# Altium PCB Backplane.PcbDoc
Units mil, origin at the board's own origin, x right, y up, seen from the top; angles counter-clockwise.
Board outline 5750 x 1500 mil, 6 copper layers (Top Layer, InternalPlane1, InternalPlane2, InternalPlane3, InternalPlane4, Bottom Layer); 11 components, 85 nets, 180 pads, 5 vias.
Unrouted connection lines stored in the file: 2.
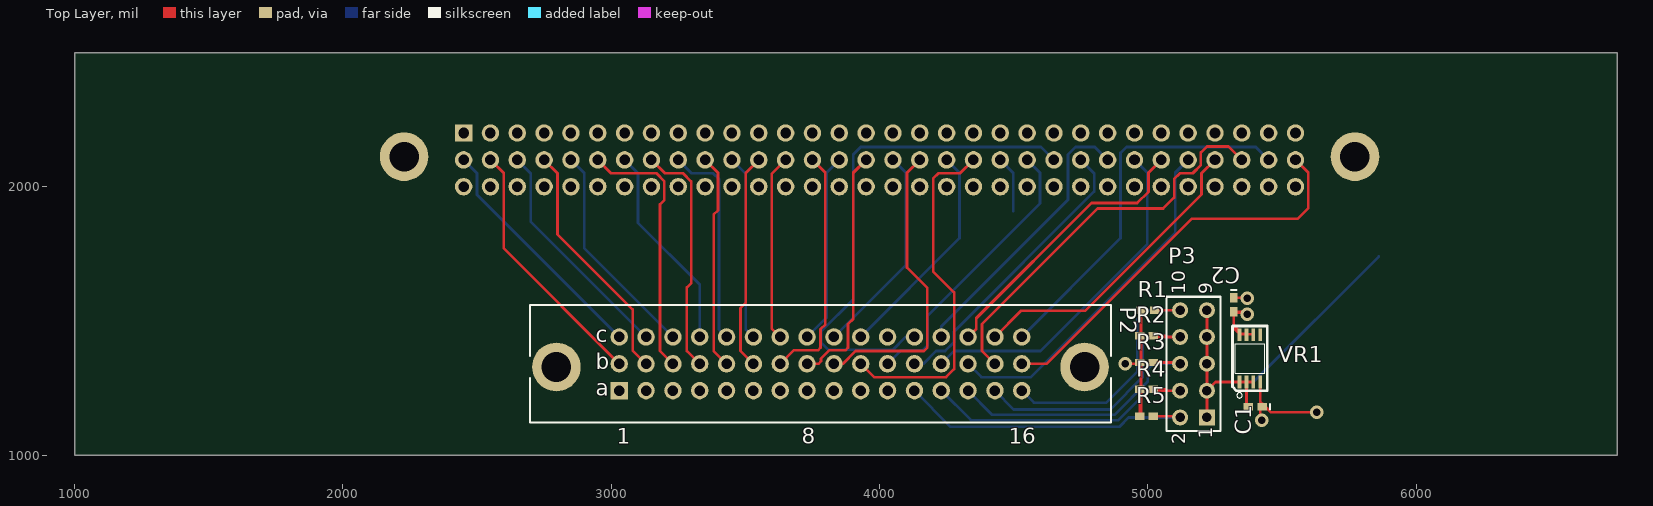
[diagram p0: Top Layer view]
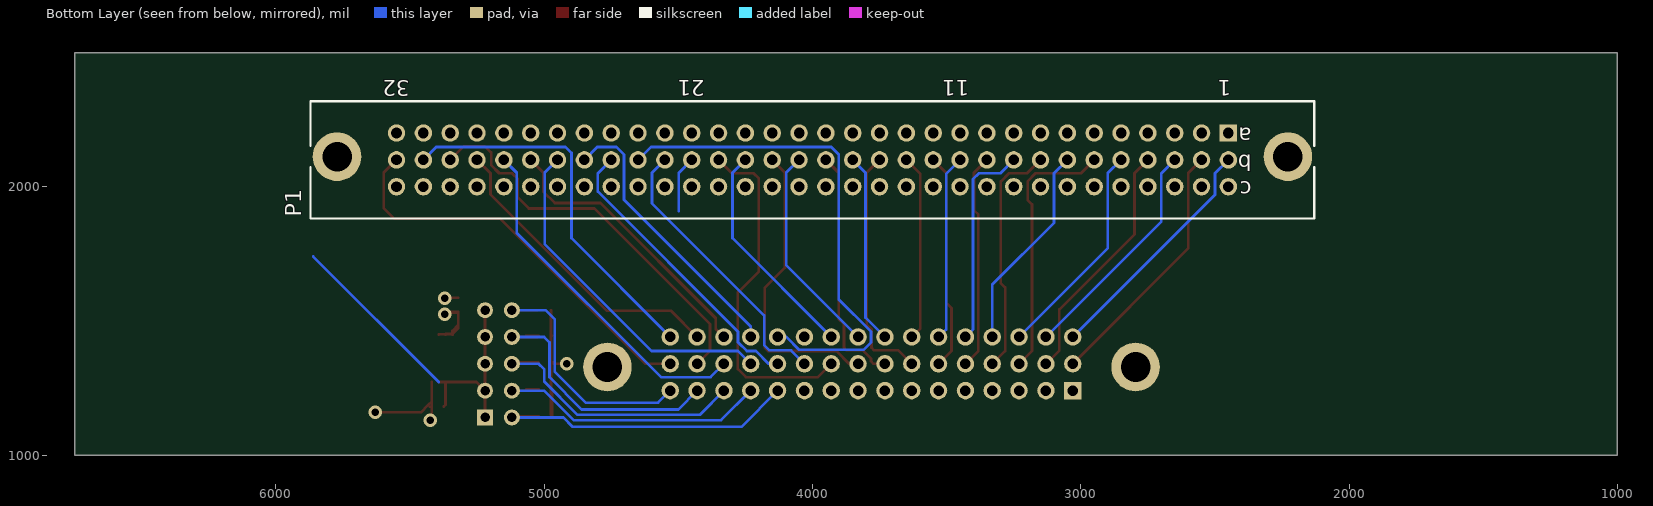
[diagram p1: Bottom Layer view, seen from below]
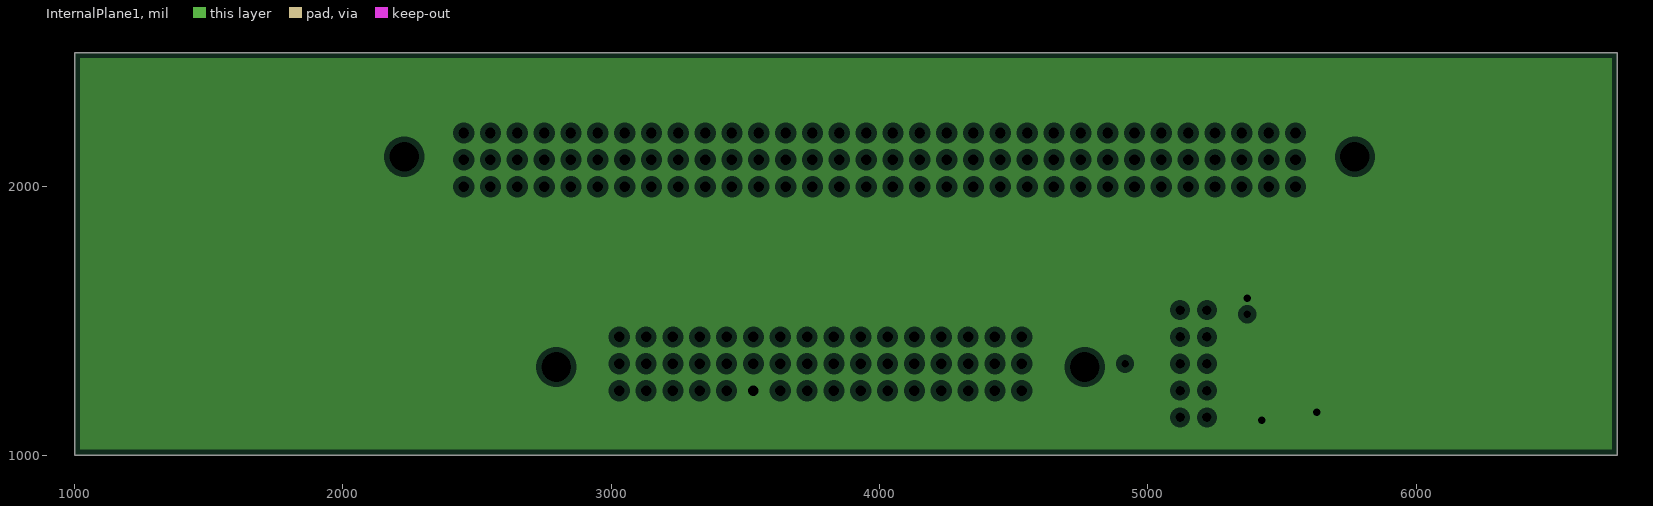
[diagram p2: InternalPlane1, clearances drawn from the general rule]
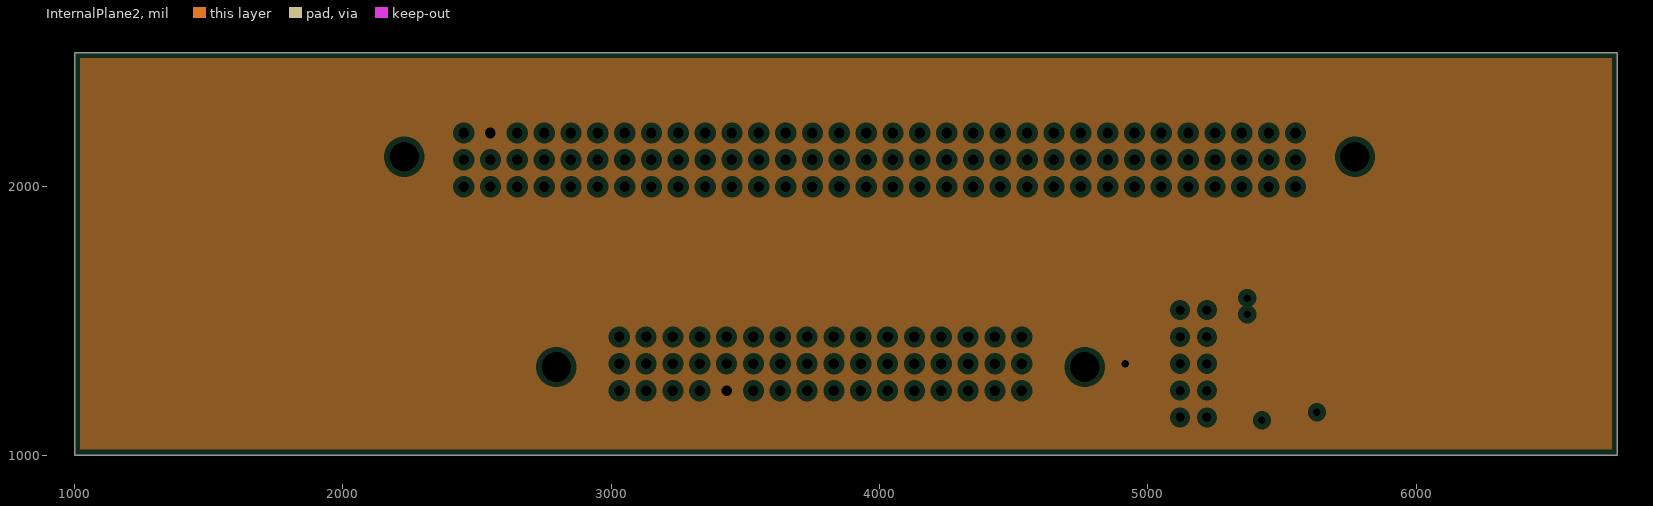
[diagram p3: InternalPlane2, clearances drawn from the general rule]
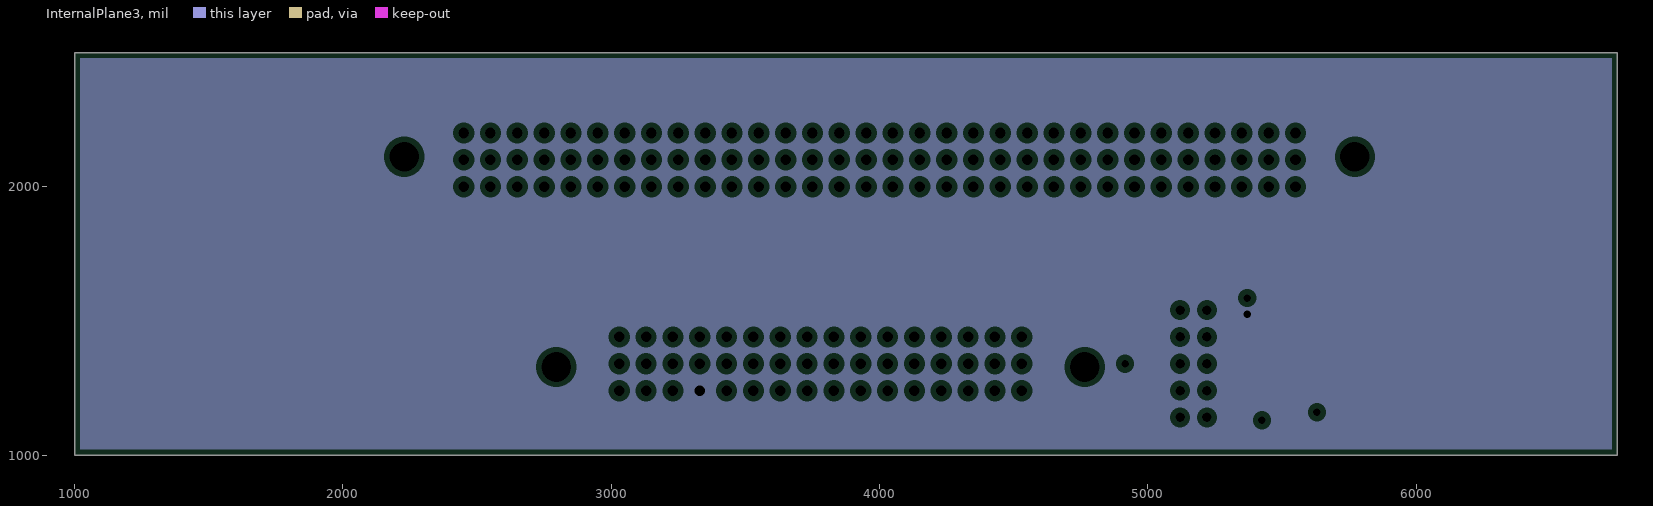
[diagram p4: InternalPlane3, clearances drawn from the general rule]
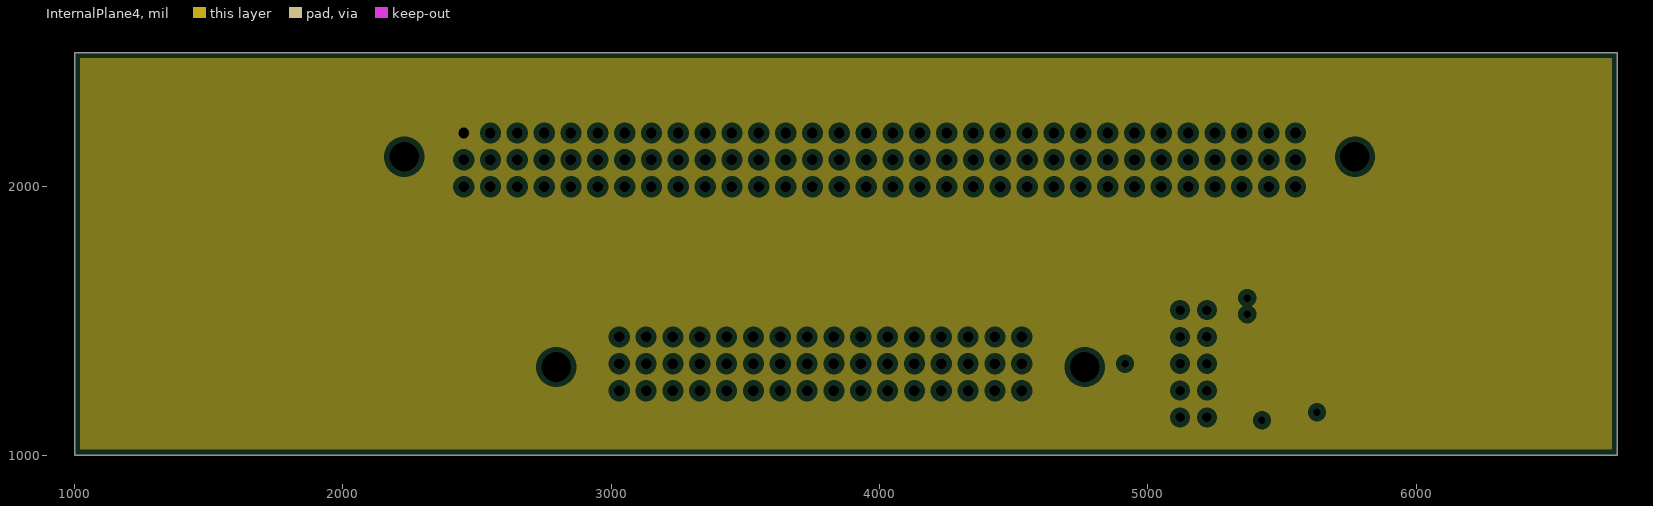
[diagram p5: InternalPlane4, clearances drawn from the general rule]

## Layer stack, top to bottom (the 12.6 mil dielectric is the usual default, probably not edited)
Top Layer: signal copper 1.4
Dielectric: core 12.6, FR-4, Dk 4.8
InternalPlane1: plane copper 1.4, net DGND
Dielectric: prepreg 12.6, FR-4, Dk 4.8
InternalPlane2: plane copper 1.4, net AGND
Dielectric: core 12.6, FR-4, Dk 4.8
InternalPlane3: plane copper 1.4, net +5V
Dielectric: prepreg 12.6, FR-4, Dk 4.8
InternalPlane4: plane copper 1.4, net VCC
Dielectric: core 12.6, FR-4, Dk 4.8
Bottom Layer: signal copper 1.4

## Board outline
1000,1000 6750,1000 6750,2500 1000,2500

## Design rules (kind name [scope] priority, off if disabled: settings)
Clearance [All] p1: gap=10
ComponentClearance [All] p1: gap=10 collisioncheckmode=3 verticalgap=10
PlaneClearance [All] p1: clearance=20
PlaneConnect [All] p1: planeconnectstyle=Relief reliefexpansion=20 reliefentries=4 reliefconductorwidth=10 reliefairgap=10
PolygonConnect [All] p1: connectstyle=Relief reliefconductorwidth=10 reliefentries=4 polygonreliefangle="90 Angle"
RoomDefinition "Digital Connector" [InComponentClass('Digital Connector')] p1: confinementstyle=ConfineIn formatcopy=TRUE lockcomponents=FALSE outline 2435,1015 5860,1015 5860,1825 2435,1825
RoomDefinition "Analog Connector" [InComponentClass('Analog Connector')] p2: confinementstyle=ConfineIn formatcopy=TRUE lockcomponents=FALSE outline 1920,1780 5940,1780 5940,2455 1920,2455
RoutingVias [All] p1: holewidth=28 width=50 viastyle="Through Hole" minholewidth=28 minwidth=50 maxholewidth=28 maxwidth=50
SolderMaskExpansion [All] p1: expansion=4
TestPointUsage [All] p1: valid=0 allowmultiple=FALSE
Testpoint [All] p1: side=15 testpointundercomponent=TRUE minsize=40 maxsize=100 preferedsize=60 minholesize=0 maxholesize=40 preferedholesize=32 testpointgrid=1 style=1023 order=0123456789
Width [All] p1: maxlimit=10 minlimit=10 preferedwidth=10
16 further rules are at their usual default settings.

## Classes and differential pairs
component class "Analog Connector": P1

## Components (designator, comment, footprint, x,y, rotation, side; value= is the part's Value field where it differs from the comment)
C1 "Kemet C1206C106K9PACTU" 0402 5400,1180 r180 top
C2 "Kemet C0402C104K8PACTU" 0402 5320,1560 r270 top
P1 "DIN41612 96 pin, Backplane" EURO2.54-2V96 4000,2100 r0 bottom
P2 "DIN41612 48 pin, Backplane" EURO2.54-2V48 3780,1340 r0 top
P3 "Header 5X2" HDR2X5 5220,1140 r90 top
R1 "Res2" 1005[0402] 5000,1540 r0 top
R2 "Res2" 1005[0402] 4995,1445 r0 top
R3 "Res2" 1005[0402] 4995,1345 r0 top
R4 "Res2" 1005[0402] 4995,1245 r0 top
R5 "Res2" 1005[0402] 4995,1145 r0 top
VR1 "Kemet C0402C102K5RACTU" RM-8 5380,1360 r0 top

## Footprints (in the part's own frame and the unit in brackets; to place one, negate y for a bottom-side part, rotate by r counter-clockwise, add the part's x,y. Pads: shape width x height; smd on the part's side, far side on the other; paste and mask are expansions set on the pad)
0402 [mm] "Chip Capacitor; Body 1.0 x 0.5 mm (LxW typ)"
  rect 0.9x0.7 smd: 1(-0.65,0) 2(0.65,0)
  silkscreen extent -1.4,-0.25 -1.4,0.25
1005[0402] [mm] "Chip Resistor; Body 1.1 x 0.5 mm (LxW typ)"
  rect 0.9x0.7 smd: 1(-0.65,0) 2(0.65,0)
EURO2.54-2V48 [mm] "Connector; DIN 41612, Type 2C, Thru-Hole; Rows a+b+c, 48 Position; Vertical"
  round 4.6 hole 2.8: 17(-25,-0.3) 18(25,-0.3)
  rect 1.65x1.65 hole 1: A1(-19.05,-2.54)
  round 1.65 hole 1: A2(-16.51,-2.54) A3(-13.97,-2.54) A4(-11.43,-2.54) A5(-8.89,-2.54) A6(-6.35,-2.54) A7(-3.81,-2.54) A8(-1.27,-2.54) A9(1.27,-2.54) A10(3.81,-2.54) A11(6.35,-2.54) A12(8.89,-2.54) A13(11.43,-2.54) A14(13.97,-2.54) A15(16.51,-2.54) A16(19.05,-2.54) B1(-19.05,0) B2(-16.51,0) B3(-13.97,0) B4(-11.43,0) B5(-8.89,0) B6(-6.35,0) B7(-3.81,0) B8(-1.27,0) B9(1.27,0) B10(3.81,0) B11(6.35,0) B12(8.89,0) B13(11.43,0) B14(13.97,0) B15(16.51,0) B16(19.05,0) C1(-19.05,2.54) C2(-16.51,2.54) C3(-13.97,2.54) C4(-11.43,2.54) C5(-8.89,2.54) C6(-6.35,2.54) C7(-3.81,2.54) C8(-1.27,2.54) C9(1.27,2.54) C10(3.81,2.54) C11(6.35,2.54) C12(8.89,2.54) C13(11.43,2.54) C14(13.97,2.54) C15(16.51,2.54) C16(19.05,2.54)
  silkscreen extent -27.5,-5.55 27.5,5.55
EURO2.54-2V96 [mm] "Connector; DIN 41612, Type C, Thru-Hole; Rows a+b+c, 96 Position; Vertical"
  round 4.6 hole 2.8: 33(-45,-0.3) 34(45,-0.3)
  rect 1.65x1.65 hole 1: A1(-39.37,-2.54)
  round 1.65 hole 1: A2(-36.83,-2.54) A3(-34.29,-2.54) A4(-31.75,-2.54) A5(-29.21,-2.54) A6(-26.67,-2.54) A7(-24.13,-2.54) A8(-21.59,-2.54) A9(-19.05,-2.54) A10(-16.51,-2.54) A11(-13.97,-2.54) A12(-11.43,-2.54) A13(-8.89,-2.54) A14(-6.35,-2.54) A15(-3.81,-2.54) A16(-1.27,-2.54) A17(1.27,-2.54) A18(3.81,-2.54) A19(6.35,-2.54) A20(8.89,-2.54) A21(11.43,-2.54) A22(13.97,-2.54) A23(16.51,-2.54) A24(19.05,-2.54) A25(21.59,-2.54) A26(24.13,-2.54) A27(26.67,-2.54) A28(29.21,-2.54) A29(31.75,-2.54) A30(34.29,-2.54) A31(36.83,-2.54) A32(39.37,-2.54) B1(-39.37,0) B2(-36.83,0) B3(-34.29,0) B4(-31.75,0) B5(-29.21,0) B6(-26.67,0) B7(-24.13,0) B8(-21.59,0) B9(-19.05,0) B10(-16.51,0) B11(-13.97,0) B12(-11.43,0) B13(-8.89,0) B14(-6.35,0) B15(-3.81,0) B16(-1.27,0) B17(1.27,0) B18(3.81,0) B19(6.35,0) B20(8.89,0) B21(11.43,0) B22(13.97,0) B23(16.51,0) B24(19.05,0) B25(21.59,0) B26(24.13,0) B27(26.67,0) B28(29.21,0) B29(31.75,0) B30(34.29,0) B31(36.83,0) B32(39.37,0) C1(-39.37,2.54) C2(-36.83,2.54) C3(-34.29,2.54) C4(-31.75,2.54) C5(-29.21,2.54) C6(-26.67,2.54) C7(-24.13,2.54) C8(-21.59,2.54) C9(-19.05,2.54) C10(-16.51,2.54) C11(-13.97,2.54) C12(-11.43,2.54) C13(-8.89,2.54) C14(-6.35,2.54) C15(-3.81,2.54) C16(-1.27,2.54) C17(1.27,2.54) C18(3.81,2.54) C19(6.35,2.54) C20(8.89,2.54) C21(11.43,2.54) C22(13.97,2.54) C23(16.51,2.54) C24(19.05,2.54) C25(21.59,2.54) C26(24.13,2.54) C27(26.67,2.54) C28(29.21,2.54) C29(31.75,2.54) C30(34.29,2.54) C31(36.83,2.54) C32(39.37,2.54)
  silkscreen extent -47.5,-5.55 47.5,5.55
HDR2X5 [mm] "Connector; Header; 5x2 Position"
  rect 1.5x1.5 hole 0.9: 1(0,0)
  round 1.5 hole 0.9: 2(0,2.54) 3(2.54,0) 4(2.54,2.54) 5(5.08,0) 6(5.08,2.54) 7(7.62,0) 8(7.62,2.54) 9(10.16,0) 10(10.16,2.54)
  silkscreen extent -1.27,-1.27 11.43,3.81
RM-8 [mil]
  rect 13.4x46.9 smd: 1(-38.6,-87.8) 2(-12.6,-87.8) 3(12.6,-87.8) 4(38.6,-87.8) 5(38.6,87.8) 6(12.6,87.8) 7(-12.6,87.8) 8(-38.6,87.8)
  silkscreen extent -65,-148 65,121

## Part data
C1 C2: library part Cap, "Capacitor"
P3: "Header, 5-Pin, Dual row"
R1 R2 R3 R4 R5: "Resistor"
VR1: library part ADP3335

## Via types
v1: diameter 50, hole 28, Top Layer to Bottom Layer, 5 vias

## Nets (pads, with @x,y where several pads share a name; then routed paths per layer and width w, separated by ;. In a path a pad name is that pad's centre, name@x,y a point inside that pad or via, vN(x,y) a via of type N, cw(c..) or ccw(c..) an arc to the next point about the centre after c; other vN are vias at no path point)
+3.3V: C1.2 P3.1 P3.3 P3.5 P3.7 P3.9 VR1.1 VR1.2 VR1.3 | length 681
  Top Layer w10: P3.1 P3.3 ; P3.9 P3.7 P3.5 P3.3 ; C1.2 5367.4,1187.01 VR1.2 ; VR1.3 VR1.2 ; P3.3 5252.2,1272.2 VR1.1 VR1.2
+5V: C2.2 P2.A4 VR1.6 VR1.7 VR1.8 | length 562.5
  Top Layer w10: 5320,1484.4 5341.4,1463 5341.4,1452.2 VR1.8@5341.4,1451 ; C2.2@5320,1530 5365,1530 5370,1530 v1@5380,1530 ; VR1.8 VR1.8@5341.4,1451 ; VR1.7 VR1.7@5367.4,1450 ; v1(5370,1525) 5360.59,1534.41 C2.2 5320,1473.6 ; VR1.6 5392.6,1450 VR1.7@5367.4,1450 ; 5320,1473.6 VR1.8@5343.6,1450 ; 5320,1473.6 VR1.8@5343.6,1450 ; 5320,1473.6 VR1.8@5343.6,1450 ; VR1.8@5341.4,1451 5342.6,1451 5367.4,1451 VR1.7@5367.4,1450 ; VR1.8@5343.6,1450 VR1.7@5367.4,1450 ; VR1.8@5343.6,1450 VR1.7@5367.4,1450 ; VR1.8@5343.6,1450 VR1.7@5367.4,1450 ; VR1.8@5343.6,1450 VR1.7@5367.4,1450 ; VR1.7@5367.4,1450 VR1.6@5390,1450 ; VR1.7@5367.4,1450 VR1.6@5390,1450 ; VR1.7@5367.4,1450 VR1.6@5390,1450 ; VR1.7@5367.4,1450 VR1.6@5390,1450
+210V: P2.A2
-5V: P2.A3
ADC_EXT1: P2.A7
ADC_EXT2: P2.A8
AGND: P1.A2 P2.A5 R1.1 R2.1 R3.1 R4.1 R5.1 | length 2129.6
  Top Layer w10: v1(4915,1340) 4964.41,1340 4964.41,1345 R3.1 4974,1345 R2.1@4974,1445 ; R5.1 4970,1145 R4.1@4970,1245 ; R4.1 R4.1@4970,1245 ; R2.1 R2.1@4974,1445 ; R4.1@4970,1245 R4.1@4974.41,1245 ; R2.1@4974,1445 R2.1@4974.41,1445 ; R5.1@4974.41,1150 R4.1@4974.41,1245 ; R5.1@4974.41,1150 R4.1@4974.41,1245 ; R5.1@4974.41,1150 R4.1@4974.41,1245 ; R5.1@4974.41,1150 R4.1@4974.41,1245 ; R4.1@4974.41,1245 R3.1@4974.41,1345 ; R4.1@4974.41,1245 R3.1@4974.41,1345 ; R4.1@4974.41,1245 R3.1@4974.41,1345 ; R4.1@4974.41,1245 R3.1@4974.41,1345 ; R4.1@4974.41,1245 R3.1@4974.41,1345 ; R3.1@4974.41,1345 R2.1@4974.41,1445 ; R3.1@4974.41,1345 R2.1@4974.41,1445 ; R3.1@4974.41,1345 R2.1@4974.41,1445 ; R3.1@4974.41,1345 R2.1@4974.41,1445 ; R3.1@4974.41,1345 R2.1@4974.41,1445 ; R2.1@4974.41,1445 R1.1 ; R2.1@4974.41,1445 R1.1 ; R2.1@4974.41,1445 R1.1 ; R2.1@4974.41,1445 R1.1 ; R2.1@4974.41,1445 R1.1
CP2201/LA: P2.A1
DGND: C1.1 C2.1 P2.A6 VR1.4 | length 837.9
  Top Layer w10: C2.1 5369.41,1585.59 v1(5370,1585) ; 5418.6,1200 5432.1,1186.51 5459.6,1159 v1(5630,1159) ; v1(5425,1130) v1@5418.6,1136.4 ; C1.1 C1.1@5418.6,1180 ; v1@5418.6,1136.4 C1.1@5418.6,1180 ; v1@5418.6,1136.4 C1.1@5418.6,1180 ; v1@5418.6,1136.4 C1.1@5418.6,1180 ; v1@5418.6,1136.4 C1.1@5418.6,1180 ; C1.1@5418.6,1180 VR1.4 ; C1.1@5418.6,1180 VR1.4 ; C1.1@5418.6,1180 VR1.4 ; C1.1@5418.6,1180 VR1.4
ID0: P2.A16 P3.10 R1.2 | length 960.2
  Top Layer w10: R1.2 P3.10
  Bottom Layer w10: P2.A16 4575,1195 4845,1195 4960,1310 4960,1505 4995,1540 P3.10
ID1: P2.A15 P3.8 R2.2 | length 1054.9
  Top Layer w10: R2.2 5067,1445 5072,1440 ; R2.2@5025.59,1440 P3.8
  Bottom Layer w10: P2.A15 4500,1170 4860,1170 4980,1290 4980,1420 5000,1440 P3.8
ID2: P2.A14 P3.6 R3.2 | length 1036.8
  Top Layer w10: R3.2 5115,1345 5120,1345 P3.6
  Bottom Layer w10: P2.A14 4420,1150 4875,1150 5000,1275 5000,1320 5020,1340 P3.6
ID3: P2.A13 P3.4 R4.2 | length 1129
  Top Layer w10: R4.2 5067,1245 5072,1240 ; R4.2@5025.59,1240 P3.4
  Bottom Layer w10: P2.A13 4340,1130 4890,1130 5000,1240 P3.4
ID4: P2.A12 P3.2 R5.2 | length 1164.8
  Top Layer w10: R5.2 5115,1145 5120,1145 P3.2
  Bottom Layer w10: P2.A12 4265,1105 4893.28,1105 4928.28,1140 P3.2
SIPMBIAS1: P1.B1 P2.C1 | length 900.2
  Bottom Layer w10: P1.B1 2500,2050 2500,1970 P2.C1
SIPMBIAS2: P1.B2 P2.B1 | length 958.8
  Top Layer w10: P1.B2 2600,2050 2600,1770 P2.B1
SIPMBIAS3: P1.B3 P2.C2 | length 858.8
  Bottom Layer w10: P1.B3 2700,2050 2700,1870 P2.C2
SIPMBIAS4: P1.B4 P2.B2 | length 917.4
  Top Layer w10: P1.B4 2800,2050 2800,1822 3080,1542 3080,1390 P2.B2
SIPMBIAS5: P1.B5 P2.C3 | length 817.4
  Bottom Layer w10: P1.B5 2900,2050 2900,1770 P2.C3
SIPMBIAS6: P1.B6 P2.B3 | length 987.6
  Top Layer w10: P1.B6 3000,2050 3168,2050 3198,2020 3198,1950 3182,1934 3182,1388 P2.B3
SIPMBIAS7: P1.B7 P2.C4 | length 776
  Bottom Layer w10: P1.B7 3100,2050 3100,1865 3330,1635 P2.C4
SIPMBIAS8: P1.B8 P2.B4 | length 887.6
  Top Layer w10: P1.B8 3200,2050 3268,2050 3298,2020 3298,1640 3282,1624 3282,1388 P2.B4
SIPMBIAS9: P1.B9 P2.C5 | length 781.4
  Bottom Layer w10: P1.B9 3300,2050 3380,2050 3402,2028 3402,1468 P2.C5
SIPMBIAS10: P1.B10 P2.B5 | length 806.4
  Top Layer w10: P1.B10 3398,2052 3398,1912 3382,1896 3382,1388 P2.B5
SIPMBIAS11: P1.B11 P2.C6 | length 693.1
  Bottom Layer w10: P1.B11 3502,2048 3502,1468 P2.C6
SIPMBIAS12: P1.B12 P2.B6 | length 808
  Top Layer w10: P2.B6 3482,1388 3482,1548 3502,1568 3502,2052 P1.B12
SIPMBIAS13: P1.B13 P2.C7 | length 694.8
  Top Layer w10: P2.C7 3598,1472 3598,2048 P1.B13
SIPMBIAS14: P1.B14 P2.B7 | length 902.2
  Top Layer w10: P2.B7 3680,1390 3770,1390 3780,1400 3780,1469 3798,1487 3798,2052 P1.B14
SIPMBIAS15: P1.B15 P2.C8 | length 709.7
  Bottom Layer w10: P2.C8 3802,1512 3802,2052 P1.B15
SIPMBIAS16: P1.B16 P2.B8 | length 911.2
  Top Layer w10: P2.B8 3772,1340 3782,1350 3782,1360 3812,1390 3872.52,1390 3882.52,1400 3882.52,1487.48 3902,1506.96 3902,2052 P1.B16
SIPMBIAS17: P1.B17 P2.C9 | length 790.9
  Bottom Layer w10: P2.C9 4098,1708 4098,2052 P1.B17
SIPMBIAS18: P1.B18 P2.B9 | length 1124.2
  Top Layer w10: P2.B9 3862.85,1340 3910.33,1387.48 4165.48,1387.48 4178,1400 4178,1622 4102,1698 4102,2052 P1.B18
SIPMBIAS19: P1.B19 P2.C10 | length 832.3
  Bottom Layer w10: P2.C10 4298,1808 4298,2052 P1.B19
SIPMBIAS20: P1.B20 P2.B10 | length 1302.4
  Top Layer w10: P2.B10 3980,1290 4248,1290 4278,1320 4278,1606 4200,1684 4200,2030 4220,2050 4300,2050 P1.B20
SIPMBIAS21: P1.B21 P2.C11 | length 873.7
  Bottom Layer w10: P1.B21 4498,2052 4498,1908 ; 5392.6,1272.2 5860.6,1740.2
SIPMBIAS22: P1.B22 P2.B11 | length 1062
  Bottom Layer w10: P2.B11 4080,1390 4160,1390 4180,1410 4180,1520 4598,1938 4598,2052 P1.B22
SIPMBIAS23: P1.B23 P2.C12 | length 1908.7
  Bottom Layer w10: P2.C12 4097.15,1440 4049.15,1392 3810,1392 3782,1420 3782,1460 3902,1580 3902,2120 3930,2148 4602,2148 P1.B23
SIPMBIAS24: P1.B24 P2.B12 | length 1097.6
  Bottom Layer w10: P2.B12 4162.85,1340 4210.33,1387.48 4244.63,1387.48 4277.48,1420.33 4277.48,1459.48 4800,1982 4800,2050 P1.B24
SIPMBIAS25: P1.B25 P2.C13 | length 1055
  Bottom Layer w10: P2.C13 4230,1479.34 4702,1951.34 4702,2120 4730,2148 4802,2148 P1.B25
SIPMBIAS26: P1.B26 P2.B13 | length 1286.6
  Bottom Layer w10: P2.B13 4278,1388 4600,1388 4998,1786 4998,2052 P1.B26
SIPMBIAS27: P1.B27 P2.C14 | length 1058
  Top Layer w10: P2.C14 4360.32,1470.32 4360.32,1509.68 4789.64,1939 4960,1939 5002,1981 5002,2052 P1.B27
SIPMBIAS28: P1.B28 P2.B14 | length 1307.4
  Bottom Layer w10: P2.B14 4380,1290 4564,1290 5102,1828 5102,2052 P1.B28
SIPMBIAS29: P1.B29 P2.C15 | length 1139.7
  Top Layer w10: P2.C15 4528,1538 4767,1538 5200,1971 5200,2050 P1.B29
SIPMBIAS30: P1.B30 P2.B15 | length 1498.3
  Top Layer w10: P2.B15 4382,1388 4382,1488 4813,1919 5057,1919 5098,1960 5098,2028 5120,2050 5167.15,2050 5197.48,2080.33 5197.48,2127.48 5220,2150 5300,2150 P1.B30
SIPMBIAS31: P1.B31 P2.C16 | length 1419.4
  Bottom Layer w10: P2.C16 4898,1808 4898,2126 4920,2148 5402,2148 P1.B31
SIPMBIAS32: P1.B32 P2.B16 | length 1508.1
  Top Layer w10: P2.B16 4623,1340 5163,1880 5558,1880 5598,1920 5598,2052 P1.B32
SIPMOUT1: P1.C1
SIPMOUT2: P1.C2
SIPMOUT3: P1.C3
SIPMOUT4: P1.C4
SIPMOUT5: P1.C5
SIPMOUT6: P1.C6
SIPMOUT7: P1.C7
SIPMOUT8: P1.C8
SIPMOUT9: P1.C9
SIPMOUT10: P1.C10
SIPMOUT11: P1.C11
SIPMOUT12: P1.C12
SIPMOUT13: P1.C13
SIPMOUT14: P1.C14
SIPMOUT15: P1.C15
SIPMOUT16: P1.C16
SIPMOUT17: P1.C17
SIPMOUT18: P1.C18
SIPMOUT19: P1.C19
SIPMOUT20: P1.C20
SIPMOUT21: P1.C21
SIPMOUT22: P1.C22
SIPMOUT23: P1.C23
SIPMOUT24: P1.C24
SIPMOUT25: P1.C25
SIPMOUT26: P1.C26
SIPMOUT27: P1.C27
SIPMOUT28: P1.C28
SIPMOUT29: P1.C29
SIPMOUT30: P1.C30
SIPMOUT31: P1.C31
SIPMOUT32: P1.C32
SUMMED1: P1.A5
SUMMED2: P1.A8
SUMMED3: P1.A13
SUMMED4: P1.A19
SUMMED5: P1.A24
SUMMED6: P1.A32
VCC: P1.A1
pads on no net: P1.33 P1.34 P1.A3 P1.A4 P1.A6 P1.A7 P1.A9 P1.A10 P1.A11 P1.A12 P1.A14 P1.A15 P1.A16 P1.A17 P1.A18 P1.A20 P1.A21 P1.A22 P1.A23 P1.A25 P1.A26 P1.A27 P1.A28 P1.A29 P1.A30 P1.A31 P2.17 P2.18 P2.A9 P2.A10 P2.A11 VR1.5

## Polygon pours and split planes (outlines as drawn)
DGND on InternalPlane1 (split plane): 6729.61,1020.39 1020.39,1020.39 1020.39,2479.61 6729.61,2479.61
AGND on InternalPlane2 (split plane): 6729.61,1020.39 1020.39,1020.39 1020.39,2479.61 6729.61,2479.61
+5V on InternalPlane3 (split plane): 6729.61,1020.39 1020.39,1020.39 1020.39,2479.61 6729.61,2479.61
VCC on InternalPlane4 (split plane): 6729.61,1020.39 1020.39,1020.39 1020.39,2479.61 6729.61,2479.61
